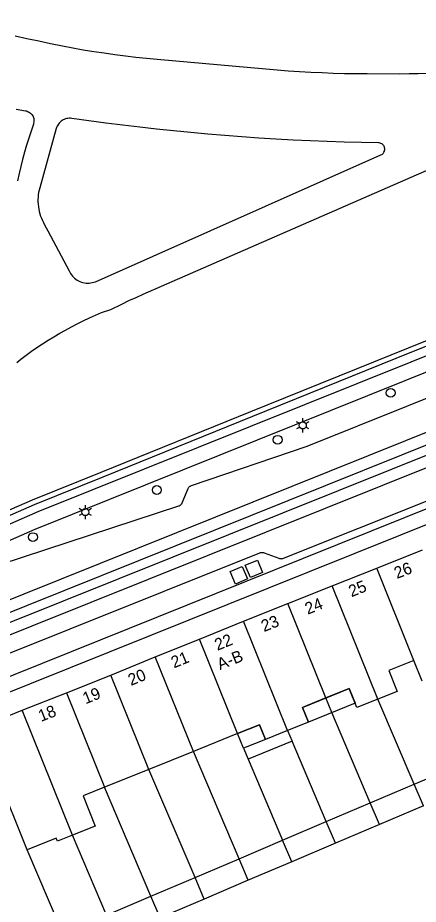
# Model space of a CAD drawing. Extents: x 122462 to 123306, y 485548 to 486417.
# Drawn here: x 123055.7 to 123106.7, y 485663.3 to 485776.1 of the extents above; entities that cross this region are included whole.
import ezdxf

# ---------------------------------------------------------------- set-up
doc = ezdxf.new("R2010")
doc.units = 0
for name, color, linetype in [('Level 1', 7, 'Continuous'), ('Level 10', 7, 'Continuous'), ('Level 17', 7, 'Continuous'), ('Level 19', 7, 'Continuous'), ('Level 2', 7, 'Continuous'), ('Level 23', 7, 'Continuous'), ('Level 37', 7, 'Continuous'), ('Level 4', 7, 'Continuous'), ('Level 42', 7, 'Continuous'), ('Level 50', 7, 'Continuous'), ('Level 53', 7, 'Continuous'), ('Level 58', 7, 'Continuous')]:
    doc.layers.add(name, color=color, linetype=linetype)

msp = doc.modelspace()

# ---------------------------------------------------------------- linework, layer by layer
at = {"layer": 'Level 1'}
for p, q in [((123101.4, 485706.05), (123107.21, 485708.37)), ((123095.75, 485703.79), (123101.4, 485706.05)), ((123090.09, 485701.53), (123095.75, 485703.79)), ((123084.44, 485699.29), (123090.09, 485701.53)), ((123078.84, 485697.03), (123084.44, 485699.29)), ((123073.23, 485694.76), (123078.84, 485697.03)), ((123067.58, 485692.45), (123073.23, 485694.76)), ((123107.2, 485691.65), (123106.13, 485694.32)), ((123061.92, 485690.17), (123067.58, 485692.45)), ((123056.3, 485687.96), (123061.92, 485690.17)), ((123056.93, 485670.21), (123050.67, 485685.74)), ((123083.69, 485685), (123078.08, 485682.74)), ((123078.08, 485682.74), (123072.42, 485680.45)), ((123072.42, 485680.45), (123066.76, 485678.17))]:
    msp.add_line(p, q, dxfattribs=at)
for points in [[(123106.13, 485694.32), (123102.93, 485693.04), (123104.01, 485690.36), (123101.56, 485689.38)], [(123101.56, 485689.38), (123098.88, 485688.3), (123097.9, 485690.72), (123094.93, 485689.53)], [(123094.93, 485689.53), (123091.96, 485688.33), (123092.71, 485686.47), (123090.04, 485685.4)], [(123050.67, 485685.74), (123053.48, 485686.85), (123056.3, 485687.96)], [(123090.04, 485685.4), (123087.24, 485684.27), (123086.49, 485686.12), (123083.69, 485685)], [(123066.76, 485678.17), (123064.04, 485677.08), (123065.58, 485673.24), (123062.69, 485672.08)], [(123062.69, 485672.08), (123060.77, 485671.3), (123060.61, 485671.69), (123056.93, 485670.21)]]:
    msp.add_lwpolyline(points, dxfattribs=at)
at = {"layer": 'Level 10'}
for points in [[(123092.71, 485686.47), (123091.96, 485688.33), (123097.9, 485690.72), (123098.65, 485688.87), (123092.71, 485686.47)], [(123084.44, 485683.14), (123083.69, 485685), (123086.49, 485686.12), (123087.24, 485684.27), (123084.44, 485683.14)]]:
    msp.add_lwpolyline(points, dxfattribs=at)
at = {"layer": 'Level 17'}
for points in [[(123306.02, 485793.23), (123281.54, 485783.41), (123199.54, 485750.48), (123092.05, 485707.28), (123051.43, 485690.97), (123010.46, 485674.56), (123010.38, 485674.54), (123010.31, 485674.53), (123010.23, 485674.54)], [(123010.9, 485672.76), (123016.12, 485674.9), (123023.42, 485677.77), (123052.25, 485689.33), (123092.64, 485705.53), (123175.87, 485738.97), (123200.14, 485748.71), (123282.24, 485781.66), (123306.02, 485791.2)], [(123033.3, 485704.16), (123033.55, 485703.56), (123043.09, 485707.71), (123057.87, 485714.13), (123066.6, 485717.66), (123085.63, 485725.38), (123105.66, 485733.48), (123130.67, 485743.46), (123153.55, 485752.61), (123177.38, 485762.27), (123193.41, 485768.64), (123221.97, 485779.99), (123224.29, 485780.91)], [(123193.77, 485767.58), (123058.27, 485713.2), (123043.56, 485706.78)], [(123194.37, 485765.79), (123057.92, 485710.97), (123044.4, 485705.07)], [(123045.06, 485703.75), (123076.2, 485713.96), (123076.3, 485713.99), (123076.38, 485714.04), (123076.46, 485714.1), (123076.53, 485714.17), (123076.59, 485714.25), (123076.63, 485714.34), (123077.4, 485716.16), (123077.45, 485716.26), (123077.51, 485716.34), (123077.58, 485716.42), (123077.66, 485716.48), (123077.74, 485716.54), (123077.84, 485716.58), (123092.54, 485721.56), (123187.75, 485759.76)], [(123050.19, 485693.45), (123086.52, 485708), (123086.63, 485708.03), (123086.75, 485708.05), (123086.87, 485708.05), (123086.98, 485708.04), (123087.09, 485708.01), (123088.94, 485707.31), (123089.03, 485707.28), (123089.14, 485707.26), (123089.24, 485707.25), (123089.34, 485707.26), (123089.45, 485707.27), (123089.55, 485707.3), (123117.89, 485718.63)]]:
    msp.add_lwpolyline(points, dxfattribs=at)
at = {"layer": 'Level 19'}
for p, q in [((123106.16, 485678.57), (123101.56, 485689.38)), ((123090.04, 485685.4), (123090.63, 485684.02)), ((123090.63, 485684.02), (123085.03, 485681.76)), ((123094.98, 485673.8), (123090.63, 485684.02)), ((123084.44, 485683.14), (123085.03, 485681.76)), ((123083.9, 485669.08), (123078.08, 485682.74)), ((123085.03, 485681.76), (123089.43, 485671.44)), ((123078.28, 485666.69), (123072.42, 485680.45)), ((123072.67, 485664.3), (123066.76, 485678.17)), ((123067.03, 485661.9), (123062.69, 485672.08)), ((123061.48, 485659.53), (123056.93, 485670.21))]:
    msp.add_line(p, q, dxfattribs=at)
for points in [[(123104.35, 485768.9), (123100.17, 485768.92), (123098.74, 485768.93), (123097.31, 485768.95), (123095.87, 485768.99), (123094.44, 485769.04), (123093.01, 485769.11), (123091.58, 485769.19), (123090.15, 485769.28), (123088.72, 485769.39), (123087.29, 485769.51), (123073.45, 485770.75), (123072.11, 485770.88), (123070.76, 485771.02), (123069.42, 485771.18), (123068.08, 485771.35), (123066.74, 485771.54), (123065.4, 485771.74), (123064.07, 485771.96), (123062.74, 485772.2), (123061.41, 485772.45), (123059.9, 485772.75), (123058.39, 485773.07), (123056.88, 485773.4), (123055.38, 485773.74)], [(123107.85, 485768.96), (123106.68, 485768.92), (123105.51, 485768.91), (123104.35, 485768.9)], [(123055.54, 485764.45), (123056.7, 485764.24), (123056.84, 485764.21), (123056.97, 485764.16), (123057.1, 485764.1), (123057.22, 485764.03), (123057.33, 485763.94), (123057.44, 485763.85), (123057.53, 485763.74), (123057.6, 485763.62), (123057.67, 485763.5), (123057.72, 485763.37), (123057.76, 485763.23), (123057.78, 485763.09), (123057.79, 485762.95), (123057.78, 485762.81), (123057.75, 485762.67), (123057.72, 485762.54), (123057.42, 485761.65), (123057.13, 485760.75), (123056.86, 485759.86), (123056.6, 485758.96), (123056.35, 485758.05), (123056.11, 485757.15), (123055.89, 485756.24), (123055.68, 485755.32)], [(123064.62, 485742.3), (123064.82, 485742.31), (123065.02, 485742.33), (123065.21, 485742.37), (123065.41, 485742.42), (123065.6, 485742.49), (123101.93, 485758.62), (123102.03, 485758.67), (123102.12, 485758.73), (123102.2, 485758.8), (123102.26, 485758.89), (123102.32, 485758.98), (123102.37, 485759.08), (123102.4, 485759.18), (123102.41, 485759.29), (123102.41, 485759.4), (123102.4, 485759.51), (123102.37, 485759.61), (123102.33, 485759.71), (123102.27, 485759.81), (123102.2, 485759.89), (123102.12, 485759.97), (123102.04, 485760.03), (123101.94, 485760.08), (123101.84, 485760.12), (123101.73, 485760.14), (123101.62, 485760.15), (123099.45, 485760.19), (123097.27, 485760.24), (123095.1, 485760.32), (123092.92, 485760.4), (123090.75, 485760.5), (123088.58, 485760.62), (123086.41, 485760.76), (123084.24, 485760.9), (123082.07, 485761.07), (123079.9, 485761.25), (123077.73, 485761.45), (123075.56, 485761.66), (123073.4, 485761.88), (123071.24, 485762.13), (123069.08, 485762.39), (123066.92, 485762.66), (123064.76, 485762.95), (123062.61, 485763.26), (123062.45, 485763.27), (123062.28, 485763.27), (123062.12, 485763.26), (123061.96, 485763.23), (123061.81, 485763.19), (123061.65, 485763.14), (123061.51, 485763.07), (123061.37, 485762.98), (123061.23, 485762.89), (123061.11, 485762.78), (123061, 485762.67), (123060.9, 485762.54), (123060.81, 485762.4), (123060.73, 485762.26), (123060.67, 485762.11), (123060.62, 485761.96), (123058.52, 485754.44), (123058.44, 485754.14), (123058.38, 485753.84), (123058.34, 485753.54), (123058.31, 485753.24), (123058.3, 485752.93), (123058.3, 485752.63), (123058.32, 485752.33), (123058.35, 485752.03), (123058.4, 485751.72), (123058.46, 485751.43), (123058.54, 485751.13), (123058.64, 485750.84), (123058.74, 485750.56), (123058.87, 485750.28), (123059, 485750.01), (123059.15, 485749.74), (123059.55, 485748.94), (123062.26, 485743.88), (123062.35, 485743.7), (123062.45, 485743.53), (123062.56, 485743.36), (123062.68, 485743.2), (123062.82, 485743.06), (123062.96, 485742.92), (123063.12, 485742.8), (123063.29, 485742.68), (123063.46, 485742.59), (123063.64, 485742.5), (123063.83, 485742.43), (123064.02, 485742.38), (123064.22, 485742.34), (123064.42, 485742.31), (123064.62, 485742.3)], [(123055.63, 485732.2), (123056.1, 485732.62), (123056.78, 485733.13), (123057.47, 485733.63), (123058.17, 485734.11), (123058.88, 485734.59), (123059.6, 485735.04), (123060.32, 485735.49), (123061.06, 485735.92), (123061.8, 485736.34), (123062.55, 485736.74), (123063.3, 485737.13), (123064.07, 485737.51), (123064.84, 485737.87), (123065.61, 485738.22), (123066.4, 485738.55), (123067.56, 485738.94), (123068.99, 485739.65), (123069.88, 485740.08), (123070.78, 485740.49), (123071.69, 485740.89), (123108.1, 485756.8)], [(123100.57, 485676.19), (123095.68, 485687.67), (123094.93, 485689.53)]]:
    msp.add_lwpolyline(points, dxfattribs=at)
at = {"layer": 'Level 2'}
for p, q in [((123106.16, 485678.57), (123111.76, 485680.96)), ((123100.57, 485676.19), (123106.16, 485678.57)), ((123107.33, 485675.83), (123106.16, 485678.57)), ((123094.98, 485673.8), (123100.57, 485676.19)), ((123101.74, 485673.45), (123100.57, 485676.19)), ((123107.33, 485675.83), (123101.74, 485673.45)), ((123089.43, 485671.44), (123094.98, 485673.8)), ((123096.15, 485671.06), (123094.98, 485673.8)), ((123101.74, 485673.45), (123096.15, 485671.06)), ((123083.9, 485669.08), (123089.43, 485671.44)), ((123090.59, 485668.7), (123089.43, 485671.44)), ((123096.15, 485671.06), (123090.59, 485668.7)), ((123078.28, 485666.69), (123083.9, 485669.08)), ((123085.06, 485666.34), (123083.9, 485669.08)), ((123090.59, 485668.7), (123085.06, 485666.34)), ((123072.67, 485664.3), (123078.28, 485666.69)), ((123079.45, 485663.95), (123078.28, 485666.69)), ((123085.06, 485666.34), (123079.45, 485663.95)), ((123067.03, 485661.9), (123072.67, 485664.3)), ((123073.84, 485661.56), (123072.67, 485664.3)), ((123079.45, 485663.95), (123073.84, 485661.56))]:
    msp.add_line(p, q, dxfattribs=at)
at = {"layer": 'Level 23'}
msp.add_lwpolyline([(123033.3, 485704.16), (123057.62, 485714.73), (123066.35, 485718.26), (123085.38, 485725.98), (123105.42, 485734.09), (123130.43, 485744.07), (123153.31, 485753.22), (123177.14, 485762.88), (123221.73, 485780.6), (123233.12, 485785.09)], dxfattribs=at)
at = {"layer": 'Level 37'}
for points in [[(123051.53, 485700.77), (123241.71, 485777.16)], [(123052.08, 485699.4), (123242.53, 485775.87)], [(123019.64, 485685.1), (123243.14, 485774.75)], [(123020.18, 485683.72), (123243.94, 485773.45)]]:
    msp.add_lwpolyline(points, dxfattribs=at)
at = {"layer": 'Level 4'}
for p, q in [((123106.13, 485694.32), (123101.4, 485706.05)), ((123101.56, 485689.38), (123095.75, 485703.79)), ((123094.93, 485689.53), (123090.09, 485701.53)), ((123090.04, 485685.4), (123084.44, 485699.29)), ((123083.69, 485685), (123078.84, 485697.03)), ((123078.08, 485682.74), (123073.23, 485694.76)), ((123072.42, 485680.45), (123067.58, 485692.45)), ((123061.92, 485690.17), (123066.76, 485678.17)), ((123062.69, 485672.08), (123056.3, 485687.96))]:
    msp.add_line(p, q, dxfattribs=at)
at = {"layer": 'Level 42'}
for points in [[(123085.33, 485704.84), (123084.67, 485706.41), (123086.22, 485707.05), (123086.87, 485705.48), (123085.33, 485704.84)], [(123083.41, 485704.03), (123082.75, 485705.6), (123084.29, 485706.24), (123084.95, 485704.67), (123083.41, 485704.03)]]:
    msp.add_lwpolyline(points, dxfattribs=at)
at = {"layer": 'Level 50'}
for p, q in [((123091.6, 485724.43), (123091.21, 485724.66)), ((123091.99, 485724.66), (123091.99, 485725.11)), ((123092.77, 485724.66), (123092.38, 485724.43)), ((123091.6, 485723.98), (123091.21, 485723.76)), ((123091.99, 485723.31), (123091.99, 485723.76)), ((123092.77, 485723.76), (123092.38, 485723.98)), ((123063.94, 485713.4), (123063.55, 485713.63)), ((123064.33, 485713.63), (123064.33, 485714.08)), ((123065.11, 485713.63), (123064.72, 485713.4)), ((123063.94, 485712.95), (123063.55, 485712.73)), ((123064.33, 485712.28), (123064.33, 485712.73)), ((123065.11, 485712.73), (123064.72, 485712.95))]:
    msp.add_line(p, q, dxfattribs=at)
for centre in [(123091.99, 485724.2), (123064.33, 485713.18)]:
    msp.add_circle(centre, 0.45, dxfattribs=at)
at = {"layer": 'Level 53'}
for centre in [(123103.17, 485728.35), (123088.8, 485722.38), (123073.42, 485715.99), (123057.66, 485710)]:
    msp.add_circle(centre, 0.56, dxfattribs=at)

# ---------------------------------------------------------------- texts
at = {"layer": 'Level 58'}
for s, rotation, p in [('26', 21.7352, (123103.97, 485704.66)), ('25', 21.7954, (123098.18, 485702.34)), ('24', 21.7747, (123092.62, 485700.12)), ('23', 21.6164, (123087.05, 485697.91)), ('22', 21.9611, (123081.13, 485695.53)), ('21', 22.0538, (123075.6, 485693.29)), ('A-B', 21.9611, (123081.45, 485693.06)), ('20', 22.2796, (123070.13, 485691.06)), ('19', 21.9391, (123064.35, 485688.72)), ('18', 21.4784, (123058.69, 485686.48))]:
    msp.add_text(s, height=1.5, rotation=rotation, dxfattribs=at).set_placement(p)

doc.saveas('drawing.dxf')
